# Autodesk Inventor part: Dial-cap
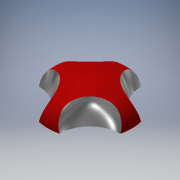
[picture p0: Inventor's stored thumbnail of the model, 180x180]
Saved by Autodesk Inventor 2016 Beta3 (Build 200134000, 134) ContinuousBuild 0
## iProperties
Shininess: 64.0
Length Units: 11272
Angle Units: 11279
Time Units: 11290
Mass Units: 11286
Length Display Precision: 3
Angle Display Precision: 2
Compacted: True
Created: 2001-11
Part Number: Dial-cap
Document SubType Name: Modeling
Designer: Autodesk, Inc.
Mass: 1.44203 g
Surface Area: 10.3598 cm^2
Volume: 1.44203 cm^3
Density: 1 g/cm^3
Material: Generic
Appearance: Smooth - Red
Density: 0.0
Volumn: 0.0
Area: 0.0
PropertySet Name: Model Information
Control State: 0
Master: False
Checked Out: False
Author: Autodesk, Inc.
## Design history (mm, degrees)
sketch "Sketch1"
  geometry: L1 (133.744, 47.494)-(133.744, 91.062); L2 (145.889, 43.525)-(145.889, 43.609); L3 (138.904, 43.525)-(145.889, 43.525); L4 (138.904, 44.319)-(138.904, 43.525); L5 (136.7, 44.319)-(138.904, 44.319); L6 (136.7, 47.494)-(136.7, 44.319); L7 (133.744, 47.494)-(136.7, 47.494); L8 (133.744, 54.846)-(133.744, 91.062); A1 r 23.812 centre (133.744, 26.857) between (141.999, 49.192) and (133.744, 50.669); A2 r 5.953 centre (139.936, 43.609) between (145.889, 43.609) and (141.999, 49.192)
  constraints: 16 end point, 4 point on circle, 4 vertical, 3 horizontal, 2 centre point, 2 point on line, 1 tangent, 1 other
revolve "RevolutionFull1" sketch "Sketch1" stored, may be unused: angle "d0" = 360 deg
sketch "Sketch3"
  geometry: A1 r 12.144 centre (0, 0) between (-2.977, -11.774) and (-11.774, -2.977) reference; A2 r 8.797 centre (-11.774, -11.774) between (-2.977, -11.774) and (-11.774, -2.977)
  constraints: 4 point on circle, 1 centre point
extrude "ExtrusionThru1" cut sketch "Sketch3" stored distance "d3" = 3.302; taper "d4" = 15 deg
pattern_circular "PolarArray1" dims angle "d7" = 360 deg
sketch "Sketch5"
  geometry: L1 (-2.887, 1.667)-(-2.887, -1.667); L2 (0, 3.334)-(-2.887, 1.667); L3 (2.887, 1.667)-(0, 3.334); L4 (2.887, -1.667)-(2.887, 1.667); L5 (0, -3.334)-(2.887, -1.667); L6 (-2.887, -1.667)-(0, -3.334)
  constraints: 12 end point, 2 parallel, 2 vertical
extrude "ExtrusionToPlane1" cut sketch "Sketch5" stored distance "d8" = 3.302; taper "d9" = 0 deg
body "Solid1"
other parameters: "d1" = 0, "d2" = 0
